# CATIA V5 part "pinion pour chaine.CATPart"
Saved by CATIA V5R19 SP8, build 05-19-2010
Part number: pinion pour chaine
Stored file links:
  G:\EU_thinkMotion\CFAO_2010\MMS_groupe1\MMS_groupe1\A reprendre\OK\rdeneffle\pinion pour chaine.CATPart

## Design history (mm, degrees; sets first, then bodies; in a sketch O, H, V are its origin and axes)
Body1 (main body)
  Sketch1 on zx-plane, origin (0, 0, 0), H (-1, 0, 0), V (0, 0, 1)
    circle A1 centre (0, 0) radius 31
    radius A1 = 31
  Pad1: profile Sketch1, direction (0, -1, 0), length 22
  Sketch2 on start face of Pad1, origin (0, 0, 0), H (-1, 0, 0), V (0, 0, 1)
    circle A1 centre (0, 0) radius 15
    circle A2 centre (0, 0) radius 31
    point P1 (0, -31)
    reference projected circle E1 centre (0, 0) radius 31 from edge [face of Pad1 from Sketch1.A1 | start face of Pad1]
    radius A1 = 15
    coincidence: A2 P1, P1 V, A2 E1
  Pocket1: profile Sketch2, direction (0, -1, 0), length 16
  Sketch3 on start face of Pad1, origin (0, 0, 0), H (-1, 0, 0), V (0, 0, 1)
    circle A1 centre (0, 0) radius 12.5
    radius A1 = 12.5
  Pocket2: profile Sketch3, direction (0, -1, 0), length 22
